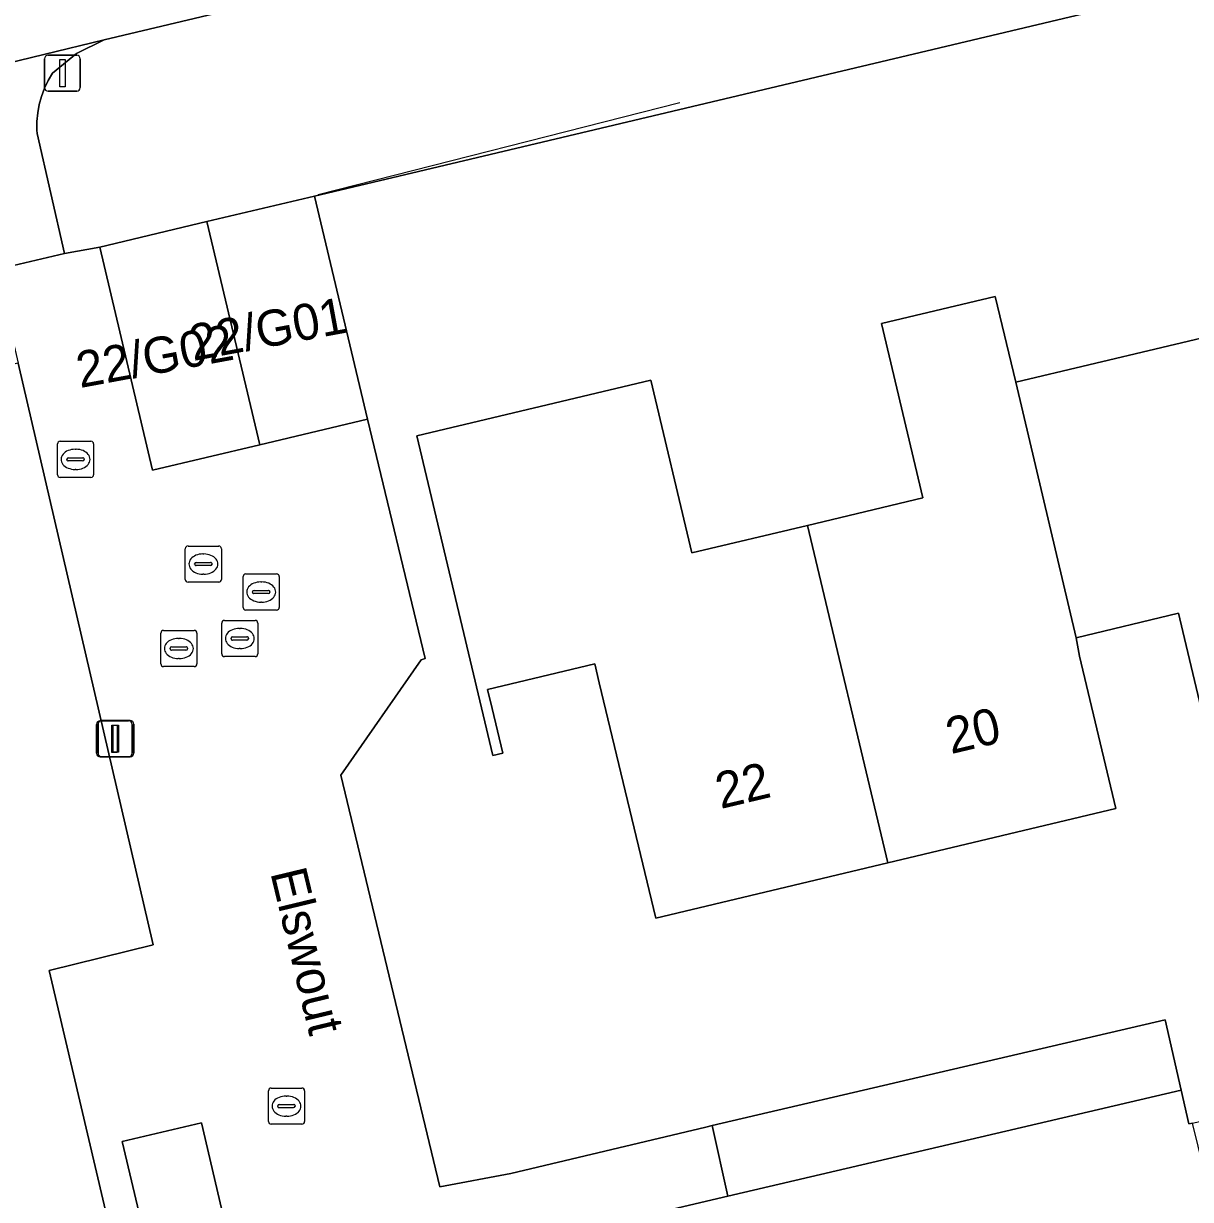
# Model space of a CAD drawing. Extents: x 157648 to 158502, y 379212 to 380938.
# Drawn here: x 158108.31 to 158140.63, y 380827.8 to 380860.36 of the extents above; entities that cross this region are included whole.
import ezdxf

# ---------------------------------------------------------------- set-up
doc = ezdxf.new("R2010")
doc.units = 0
for name, color, linetype in [('IMGEO_Brandkraan', 7, 'Continuous'), ('IMGEO_Erf', 7, 'Continuous'), ('IMGEO_Groenvoorziening', 7, 'Continuous'), ('IMGEO_Kolk', 7, 'Continuous'), ('IMGEO_Lichtmast', 7, 'Continuous'), ('IMGEO_Muur', 7, 'Continuous'), ('IMGEO_Openbare_ruimte_label', 7, 'Continuous'), ('IMGEO_Pand', 7, 'Continuous'), ('IMGEO_Pand_nummerreeks', 7, 'Continuous'), ('IMGEO_Parkeervlak_open', 7, 'Continuous'), ('IMGEO_Rijbaan_lokaal_open', 7, 'Continuous'), ('IMGEO_Rioolput', 7, 'Continuous'), ('IMGEO_Voetpad_open', 7, 'Continuous')]:
    doc.layers.add(name, color=color, linetype=linetype)

msp = doc.modelspace()

# ---------------------------------------------------------------- linework, layer by layer
at = {"layer": 'IMGEO_Brandkraan'}
for p, q in [((158109.249, 380847.863), (158109.249, 380848.715)), ((158109.324, 380848.789), (158110.176, 380848.789)), ((158109.737, 380848.569), (158109.762, 380848.569)), ((158110.25, 380848.715), (158110.25, 380847.863)), ((158109.508, 380848.283), (158109.508, 380848.295)), ((158109.946, 380848.246), (158109.548, 380848.246)), ((158109.551, 380848.332), (158109.949, 380848.332)), ((158109.992, 380848.295), (158109.992, 380848.283)), ((158109.76, 380848.009), (158109.735, 380848.009)), ((158110.176, 380847.789), (158109.324, 380847.789))]:
    msp.add_line(p, q, dxfattribs=at)
for points in [[(158109.249, 380847.863), (158109.249, 380848.715)], [(158109.324, 380848.789), (158110.176, 380848.789)], [(158110.25, 380848.715), (158110.25, 380847.863)], [(158110.176, 380847.789), (158109.324, 380847.789)]]:
    msp.add_lwpolyline(points, dxfattribs=at)
for centre, radius, start, end in [((158109.326, 380848.713), 0.0765, 91.552, 178.448), ((158109.326, 380848.713), 0.0765, 91.552, 178.448), ((158110.174, 380848.713), 0.0765, 1.552, 88.448), ((158110.174, 380848.713), 0.0765, 1.552, 88.448), ((158109.548, 380848.292), 0.0403, 85.8775, 175.7526), ((158109.545, 380848.282), 0.0366, 178.938, 274.7102), ((158109.949, 380848.289), 0.043, 264.8664, 352.4533), ((158109.953, 380848.294), 0.0386, 1.7309, 96.639), ((158109.326, 380847.865), 0.0765, 181.552, 268.448), ((158109.326, 380847.865), 0.0765, 181.552, 268.448), ((158110.174, 380847.865), 0.0765, 271.552, 358.448), ((158110.174, 380847.865), 0.0765, 271.552, 358.448)]:
    msp.add_arc(centre, radius, start, end, dxfattribs=at)
for centre, major_axis, ratio, start_param, end_param in [((158109.736, 380848.289), (-0.387, 0.002), 0.722429, 4.712389, 7.853982), ((158109.761, 380848.289), (-0.39, 0.002), 0.717154, 1.570796, 4.712389)]:
    msp.add_ellipse(centre, major_axis=major_axis, ratio=ratio, start_param=start_param, end_param=end_param, dxfattribs=at)
at = {"layer": 'IMGEO_Erf'}
for points in [[(158157.175, 380851.512), (158156.948, 380851.458), (158155.477, 380857.617), (158158.457, 380858.321), (158161.437, 380859.026), (158160.042, 380865.13), (158159.844, 380865.897), (158116.365, 380855.58), (158117.831, 380849.402), (158119.428, 380842.771), (158119.322, 380842.743), (158117.095, 380839.543), (158119.836, 380828.149), (158121.806, 380828.52), (158127.204, 380829.803), (158127.381, 380829.845), (158133.395, 380831.251), (158139.93, 380832.775), (158140.373, 380830.824), (158140.585, 380829.891), (158140.683, 380829.906), (158143.629, 380830.615), (158156.186, 380833.568), (158159.045, 380834.252)], [(158141.979, 380836.967), (158140.418, 380843.524), (158140.298, 380844.027), (158137.459, 380843.35), (158137.56, 380842.844), (158138.565, 380838.623), (158132.244, 380837.118), (158125.818, 380835.588), (158124.255, 380842.101), (158124.129, 380842.626), (158121.162, 380841.919), (158121.287, 380841.394), (158121.581, 380840.158), (158121.308, 380840.093), (158119.202, 380848.936), (158125.682, 380850.478), (158126.82, 380845.7), (158130.018, 380846.461), (158133.216, 380847.223), (158132.068, 380852.048), (158135.223, 380852.799), (158135.789, 380850.422), (158141.859, 380851.867)], [(158112.661, 380818.608), (158109.015, 380834.139), (158111.901, 380834.843), (158108.155, 380850.952), (158098.578, 380848.911), (158098.721, 380848.273), (158081.927, 380844.31), (158083.842, 380835.218), (158083.573, 380834.808), (158085.236, 380827.701), (158085.65, 380825.523), (158085.654, 380825.501), (158080.898, 380824.355), (158081.233, 380821.82), (158083.782, 380822.407), (158084.461, 380819.455), (158081.913, 380818.868), (158082.159, 380817.801), (158083.472, 380818.135), (158085.867, 380807.201), (158095.372, 380809.473), (158110.763, 380813.16)]]:
    msp.add_lwpolyline(points, dxfattribs=at)
at = {"layer": 'IMGEO_Groenvoorziening'}
msp.add_lwpolyline([(158146.125, 380868.106), (158139.634, 380866.932), (158126.077, 380863.592), (158110.544, 380859.909), (158109.774, 380859.528), (158109.114, 380858.978), (158108.993, 380858.775), (158108.89, 380858.562), (158108.807, 380858.34), (158108.744, 380858.112), (158108.701, 380857.88), (158108.68, 380857.644), (158108.679, 380857.408), (158108.685, 380857.316), (158109.447, 380853.986), (158110.419, 380854.164), (158113.387, 380854.873), (158116.365, 380855.58), (158159.844, 380865.897)], dxfattribs=at)
at = {"layer": 'IMGEO_Kolk'}
for p, q in [((158112.11, 380842.626), (158112.11, 380843.478)), ((158112.185, 380843.552), (158113.037, 380843.552)), ((158112.598, 380843.332), (158112.623, 380843.332)), ((158113.111, 380843.478), (158113.111, 380842.626)), ((158112.369, 380843.046), (158112.369, 380843.058)), ((158112.807, 380843.009), (158112.409, 380843.009)), ((158112.412, 380843.095), (158112.81, 380843.095)), ((158112.853, 380843.058), (158112.853, 380843.046)), ((158112.621, 380842.772), (158112.596, 380842.772)), ((158113.037, 380842.552), (158112.185, 380842.552)), ((158115.091, 380829.956), (158115.091, 380830.808)), ((158115.166, 380830.882), (158116.018, 380830.882)), ((158115.579, 380830.662), (158115.604, 380830.662)), ((158116.092, 380830.808), (158116.092, 380829.956)), ((158115.35, 380830.376), (158115.35, 380830.388)), ((158115.788, 380830.339), (158115.39, 380830.339)), ((158115.393, 380830.425), (158115.791, 380830.425)), ((158115.834, 380830.388), (158115.834, 380830.376)), ((158115.602, 380830.102), (158115.577, 380830.102)), ((158116.018, 380829.882), (158115.166, 380829.882))]:
    msp.add_line(p, q, dxfattribs=at)
for points in [[(158112.11, 380842.626), (158112.11, 380843.478)], [(158112.185, 380843.552), (158113.037, 380843.552)], [(158113.111, 380843.478), (158113.111, 380842.626)], [(158113.037, 380842.552), (158112.185, 380842.552)], [(158115.091, 380829.956), (158115.091, 380830.808)], [(158115.166, 380830.882), (158116.018, 380830.882)], [(158116.092, 380830.808), (158116.092, 380829.956)], [(158116.018, 380829.882), (158115.166, 380829.882)]]:
    msp.add_lwpolyline(points, dxfattribs=at)
for centre, radius, start, end in [((158112.187, 380843.476), 0.0765, 91.552, 178.448), ((158112.187, 380843.476), 0.0765, 91.552, 178.448), ((158113.035, 380843.476), 0.0765, 1.552, 88.448), ((158113.035, 380843.476), 0.0765, 1.552, 88.448), ((158112.409, 380843.055), 0.0403, 85.8775, 175.7526), ((158112.406, 380843.045), 0.0366, 178.938, 274.7102), ((158112.81, 380843.052), 0.043, 264.8664, 352.4533), ((158112.814, 380843.057), 0.0386, 1.7309, 96.639), ((158112.187, 380842.628), 0.0765, 181.552, 268.448), ((158112.187, 380842.628), 0.0765, 181.552, 268.448), ((158113.035, 380842.628), 0.0765, 271.552, 358.448), ((158113.035, 380842.628), 0.0765, 271.552, 358.448), ((158115.168, 380830.806), 0.0765, 91.552, 178.448), ((158115.168, 380830.806), 0.0765, 91.552, 178.448), ((158116.016, 380830.806), 0.0765, 1.552, 88.448), ((158116.016, 380830.806), 0.0765, 1.552, 88.448), ((158115.39, 380830.385), 0.0403, 85.8775, 175.7526), ((158115.387, 380830.375), 0.0366, 178.938, 274.7102), ((158115.791, 380830.382), 0.043, 264.8664, 352.4533), ((158115.795, 380830.387), 0.0386, 1.7309, 96.639), ((158115.168, 380829.958), 0.0765, 181.552, 268.448), ((158115.168, 380829.958), 0.0765, 181.552, 268.448), ((158116.016, 380829.958), 0.0765, 271.552, 358.448), ((158116.016, 380829.958), 0.0765, 271.552, 358.448)]:
    msp.add_arc(centre, radius, start, end, dxfattribs=at)
for centre, major_axis, ratio, start_param, end_param in [((158112.597, 380843.052), (-0.387, 0.002), 0.722429, 4.712389, 7.853982), ((158112.622, 380843.052), (-0.39, 0.002), 0.717154, 1.570796, 4.712389), ((158115.578, 380830.382), (-0.387, 0.002), 0.722429, 4.712389, 7.853982), ((158115.603, 380830.382), (-0.39, 0.002), 0.717154, 1.570796, 4.712389)]:
    msp.add_ellipse(centre, major_axis=major_axis, ratio=ratio, start_param=start_param, end_param=end_param, dxfattribs=at)
at = {"layer": 'IMGEO_Lichtmast'}
for p, q in [((158108.89, 380858.581), (158108.89, 380859.381)), ((158108.89, 380859.381), (158108.89, 380858.581)), ((158108.99, 380859.481), (158109.78, 380859.481)), ((158109.78, 380859.481), (158108.99, 380859.481)), ((158109.88, 380859.381), (158109.88, 380858.581)), ((158109.88, 380858.581), (158109.88, 380859.381)), ((158109.78, 380858.481), (158108.99, 380858.481)), ((158108.99, 380858.481), (158109.78, 380858.481)), ((158110.43, 380841.051), (158111.22, 380841.051)), ((158111.22, 380841.051), (158110.43, 380841.051)), ((158110.471, 380841.056), (158111.261, 380841.056)), ((158111.261, 380841.056), (158110.471, 380841.056)), ((158110.33, 380840.151), (158110.33, 380840.951)), ((158110.33, 380840.951), (158110.33, 380840.151)), ((158110.371, 380840.156), (158110.371, 380840.956)), ((158110.371, 380840.956), (158110.371, 380840.156)), ((158111.32, 380840.951), (158111.32, 380840.151)), ((158111.32, 380840.151), (158111.32, 380840.951)), ((158111.361, 380840.956), (158111.361, 380840.156)), ((158111.361, 380840.156), (158111.361, 380840.956)), ((158111.22, 380840.051), (158110.43, 380840.051)), ((158110.43, 380840.051), (158111.22, 380840.051)), ((158111.261, 380840.056), (158110.471, 380840.056)), ((158110.471, 380840.056), (158111.261, 380840.056))]:
    msp.add_line(p, q, dxfattribs=at)
for points in [[(158109.31, 380859.356), (158109.46, 380859.356), (158109.46, 380858.606), (158109.31, 380858.606), (158109.31, 380859.356)], [(158110.75, 380840.926), (158110.9, 380840.926), (158110.9, 380840.176), (158110.75, 380840.176), (158110.75, 380840.926)], [(158110.791, 380840.931), (158110.941, 380840.931), (158110.941, 380840.181), (158110.791, 380840.181), (158110.791, 380840.931)]]:
    msp.add_lwpolyline(points, dxfattribs=at)
for centre, start, end in [((158108.99, 380859.381), 90, 180), ((158108.99, 380859.381), 90, 180), ((158109.78, 380859.381), 0, 90), ((158109.78, 380859.381), 360, 90), ((158108.99, 380858.581), 180, 270), ((158108.99, 380858.581), 180, 270), ((158109.78, 380858.581), 270, 0), ((158109.78, 380858.581), 270, 0), ((158110.43, 380840.951), 90, 180), ((158110.43, 380840.951), 90, 180), ((158110.471, 380840.956), 90, 180), ((158110.471, 380840.956), 90, 180), ((158111.22, 380840.951), 0, 90), ((158111.22, 380840.951), 360, 90), ((158111.261, 380840.956), 0, 90), ((158111.261, 380840.956), 360, 90), ((158110.43, 380840.151), 180, 270), ((158110.43, 380840.151), 180, 270), ((158110.471, 380840.156), 180, 270), ((158110.471, 380840.156), 180, 270), ((158111.22, 380840.151), 270, 0), ((158111.22, 380840.151), 270, 0), ((158111.261, 380840.156), 270, 0), ((158111.261, 380840.156), 270, 0)]:
    msp.add_arc(centre, 0.1, start, end, dxfattribs=at)
at = {"layer": 'IMGEO_Muur'}
for points in [[(158116.466, 380855.618), (158126.49, 380858.168)], [(158117.831, 380849.402), (158119.428, 380842.771), (158119.322, 380842.743), (158117.095, 380839.543), (158119.836, 380828.149), (158121.806, 380828.52)], [(158127.381, 380829.845), (158133.395, 380831.251)], [(158127.204, 380829.803), (158127.381, 380829.845)]]:
    msp.add_lwpolyline(points, dxfattribs=at)
at = {"layer": 'IMGEO_Pand'}
for points in [[(158114.854, 380848.695), (158117.831, 380849.402), (158116.365, 380855.58), (158113.387, 380854.873)], [(158114.854, 380848.695), (158113.387, 380854.873), (158110.419, 380854.164), (158111.876, 380847.987)], [(158135.789, 380850.422), (158135.223, 380852.799), (158132.068, 380852.048), (158133.216, 380847.223), (158130.018, 380846.461), (158132.244, 380837.118), (158138.565, 380838.623), (158137.56, 380842.844), (158137.459, 380843.35)], [(158135.789, 380850.422), (158137.459, 380843.35), (158140.298, 380844.027), (158140.418, 380843.524), (158141.979, 380836.967), (158148.474, 380838.514), (158146.26, 380847.797), (158143.012, 380847.024), (158141.859, 380851.867)], [(158132.244, 380837.118), (158130.018, 380846.461), (158126.82, 380845.7), (158125.682, 380850.478), (158119.202, 380848.936), (158121.308, 380840.093), (158121.581, 380840.158), (158121.287, 380841.394), (158121.162, 380841.919), (158124.129, 380842.626), (158124.255, 380842.101), (158125.818, 380835.588)]]:
    msp.add_lwpolyline(points, close=True, dxfattribs=at)
at = {"layer": 'IMGEO_Parkeervlak_open'}
for points in [[(158140.373, 380830.824), (158139.93, 380832.775), (158133.395, 380831.251), (158127.381, 380829.845), (158127.817, 380827.893)], [(158114.479, 380824.622), (158113.239, 380829.916), (158111.04, 380829.398), (158113.552, 380818.819), (158115.724, 380819.327)]]:
    msp.add_lwpolyline(points, close=True, dxfattribs=at)
at = {"layer": 'IMGEO_Rijbaan_lokaal_open'}
msp.add_lwpolyline([(158161.859, 380827.082), (158166.548, 380828.16), (158162.99, 380842.997), (158164.297, 380846.741), (158162.89, 380852.878), (158159.911, 380852.166), (158157.175, 380851.512), (158158.697, 380845.03), (158160.721, 380836.488), (158161.619, 380832.72), (158156.661, 380831.619), (158144.102, 380828.693), (158141.156, 380827.996), (158140.683, 380829.906), (158140.585, 380829.891), (158140.373, 380830.824), (158127.817, 380827.893), (158116.939, 380825.329)], dxfattribs=at)
at = {"layer": 'IMGEO_Rioolput'}
for p, q in [((158112.864, 380845.89), (158113.716, 380845.89)), ((158112.789, 380844.964), (158112.789, 380845.816)), ((158113.277, 380845.67), (158113.302, 380845.67)), ((158113.79, 380845.816), (158113.79, 380844.964)), ((158113.048, 380845.384), (158113.048, 380845.396)), ((158113.486, 380845.347), (158113.088, 380845.347)), ((158113.091, 380845.433), (158113.489, 380845.433)), ((158113.532, 380845.396), (158113.532, 380845.384)), ((158113.3, 380845.11), (158113.275, 380845.11)), ((158114.391, 380844.19), (158114.391, 380845.042)), ((158114.466, 380845.116), (158115.318, 380845.116)), ((158114.879, 380844.896), (158114.904, 380844.896)), ((158115.392, 380845.042), (158115.392, 380844.19)), ((158113.716, 380844.89), (158112.864, 380844.89)), ((158114.65, 380844.61), (158114.65, 380844.622)), ((158115.088, 380844.573), (158114.69, 380844.573)), ((158114.693, 380844.659), (158115.091, 380844.659)), ((158115.134, 380844.622), (158115.134, 380844.61)), ((158114.902, 380844.336), (158114.877, 380844.336)), ((158115.318, 380844.116), (158114.466, 380844.116)), ((158113.798, 380842.903), (158113.798, 380843.755)), ((158113.873, 380843.829), (158114.725, 380843.829)), ((158114.286, 380843.609), (158114.311, 380843.609)), ((158114.799, 380843.755), (158114.799, 380842.903)), ((158114.057, 380843.323), (158114.057, 380843.335)), ((158114.495, 380843.286), (158114.097, 380843.286)), ((158114.1, 380843.372), (158114.498, 380843.372)), ((158114.541, 380843.335), (158114.541, 380843.323)), ((158114.309, 380843.049), (158114.284, 380843.049)), ((158114.725, 380842.829), (158113.873, 380842.829))]:
    msp.add_line(p, q, dxfattribs=at)
for points in [[(158112.864, 380845.89), (158113.716, 380845.89)], [(158112.789, 380844.964), (158112.789, 380845.816)], [(158113.79, 380845.816), (158113.79, 380844.964)], [(158114.391, 380844.19), (158114.391, 380845.042)], [(158114.466, 380845.116), (158115.318, 380845.116)], [(158115.392, 380845.042), (158115.392, 380844.19)], [(158113.716, 380844.89), (158112.864, 380844.89)], [(158115.318, 380844.116), (158114.466, 380844.116)], [(158113.798, 380842.903), (158113.798, 380843.755)], [(158113.873, 380843.829), (158114.725, 380843.829)], [(158114.799, 380843.755), (158114.799, 380842.903)], [(158114.725, 380842.829), (158113.873, 380842.829)]]:
    msp.add_lwpolyline(points, dxfattribs=at)
for centre, radius, start, end in [((158112.866, 380845.814), 0.0765, 91.552, 178.448), ((158112.866, 380845.814), 0.0765, 91.552, 178.448), ((158113.714, 380845.814), 0.0765, 1.552, 88.448), ((158113.714, 380845.814), 0.0765, 1.552, 88.448), ((158113.088, 380845.393), 0.0403, 85.8775, 175.7526), ((158113.085, 380845.383), 0.0366, 178.938, 274.7102), ((158113.489, 380845.39), 0.043, 264.8664, 352.4533), ((158113.493, 380845.395), 0.0386, 1.7309, 96.639), ((158112.866, 380844.966), 0.0765, 181.552, 268.448), ((158112.866, 380844.966), 0.0765, 181.552, 268.448), ((158113.714, 380844.966), 0.0765, 271.552, 358.448), ((158113.714, 380844.966), 0.0765, 271.552, 358.448), ((158114.468, 380845.04), 0.0765, 91.552, 178.448), ((158114.468, 380845.04), 0.0765, 91.552, 178.448), ((158115.316, 380845.04), 0.0765, 1.552, 88.448), ((158115.316, 380845.04), 0.0765, 1.552, 88.448), ((158114.69, 380844.619), 0.0403, 85.8775, 175.7526), ((158114.687, 380844.609), 0.0366, 178.938, 274.7102), ((158115.091, 380844.616), 0.043, 264.8664, 352.4533), ((158115.095, 380844.621), 0.0386, 1.7309, 96.639), ((158114.468, 380844.192), 0.0765, 181.552, 268.448), ((158114.468, 380844.192), 0.0765, 181.552, 268.448), ((158115.316, 380844.192), 0.0765, 271.552, 358.448), ((158115.316, 380844.192), 0.0765, 271.552, 358.448), ((158113.875, 380843.753), 0.0765, 91.552, 178.448), ((158113.875, 380843.753), 0.0765, 91.552, 178.448), ((158114.723, 380843.753), 0.0765, 1.552, 88.448), ((158114.723, 380843.753), 0.0765, 1.552, 88.448), ((158114.097, 380843.332), 0.0403, 85.8775, 175.7526), ((158114.094, 380843.322), 0.0366, 178.938, 274.7102), ((158114.498, 380843.329), 0.043, 264.8664, 352.4533), ((158114.502, 380843.334), 0.0386, 1.7309, 96.639), ((158113.875, 380842.905), 0.0765, 181.552, 268.448), ((158113.875, 380842.905), 0.0765, 181.552, 268.448), ((158114.723, 380842.905), 0.0765, 271.552, 358.448), ((158114.723, 380842.905), 0.0765, 271.552, 358.448)]:
    msp.add_arc(centre, radius, start, end, dxfattribs=at)
for centre, major_axis, ratio, start_param, end_param in [((158113.276, 380845.39), (-0.387, 0.002), 0.722429, 4.712389, 7.853982), ((158113.301, 380845.39), (-0.39, 0.002), 0.717154, 1.570796, 4.712389), ((158114.878, 380844.616), (-0.387, 0.002), 0.722429, 4.712389, 7.853982), ((158114.903, 380844.616), (-0.39, 0.002), 0.717154, 1.570796, 4.712389), ((158114.285, 380843.329), (-0.387, 0.002), 0.722429, 4.712389, 7.853982), ((158114.31, 380843.329), (-0.39, 0.002), 0.717154, 1.570796, 4.712389)]:
    msp.add_ellipse(centre, major_axis=major_axis, ratio=ratio, start_param=start_param, end_param=end_param, dxfattribs=at)
at = {"layer": 'IMGEO_Voetpad_open'}
msp.add_lwpolyline([(158103.851, 380858.283), (158110.544, 380859.909), (158126.077, 380863.592), (158139.634, 380866.932), (158146.125, 380868.106)], dxfattribs=at)
for points in [[(158108.685, 380857.316), (158108.679, 380857.408), (158108.68, 380857.644), (158108.701, 380857.88), (158108.744, 380858.112), (158108.807, 380858.34), (158108.89, 380858.562), (158108.993, 380858.775), (158109.114, 380858.978), (158109.774, 380859.528), (158110.544, 380859.909), (158103.851, 380858.283), (158105.184, 380858.238), (158106.075, 380857.75), (158106.623, 380856.84), (158106.896, 380856.365), (158107.22, 380854.93), (158107.551, 380853.548), (158109.447, 380853.986)], [(158127.817, 380827.893), (158127.381, 380829.845), (158127.204, 380829.803), (158121.806, 380828.52), (158119.836, 380828.149), (158117.095, 380839.543), (158119.322, 380842.743), (158119.428, 380842.771), (158117.831, 380849.402), (158114.854, 380848.695), (158111.876, 380847.987), (158110.419, 380854.164), (158109.447, 380853.986), (158107.551, 380853.548), (158108.155, 380850.952), (158111.901, 380834.843), (158109.015, 380834.139), (158112.661, 380818.608), (158113.552, 380818.819), (158111.04, 380829.398), (158113.239, 380829.916), (158114.479, 380824.622), (158116.965, 380825.228), (158116.939, 380825.329)]]:
    msp.add_lwpolyline(points, close=True, dxfattribs=at)

# ---------------------------------------------------------------- texts
at = {"layer": 'IMGEO_Openbare_ruimte_label'}
msp.add_text('Elswout', height=1, rotation=283.5359, dxfattribs=at).set_placement((158115.14, 380836.848))
at = {"layer": 'IMGEO_Pand_nummerreeks'}
for s, rotation, p in [('22/G01', 10.4915, (158113.005, 380851.011)), ('22/G02', 10.4915, (158109.873, 380850.262)), ('20', 13.3925, (158133.995, 380840.125)), ('22', 13.3925, (158127.615, 380838.606))]:
    msp.add_text(s, height=1, rotation=rotation, dxfattribs=at).set_placement(p)

doc.saveas('drawing.dxf')
